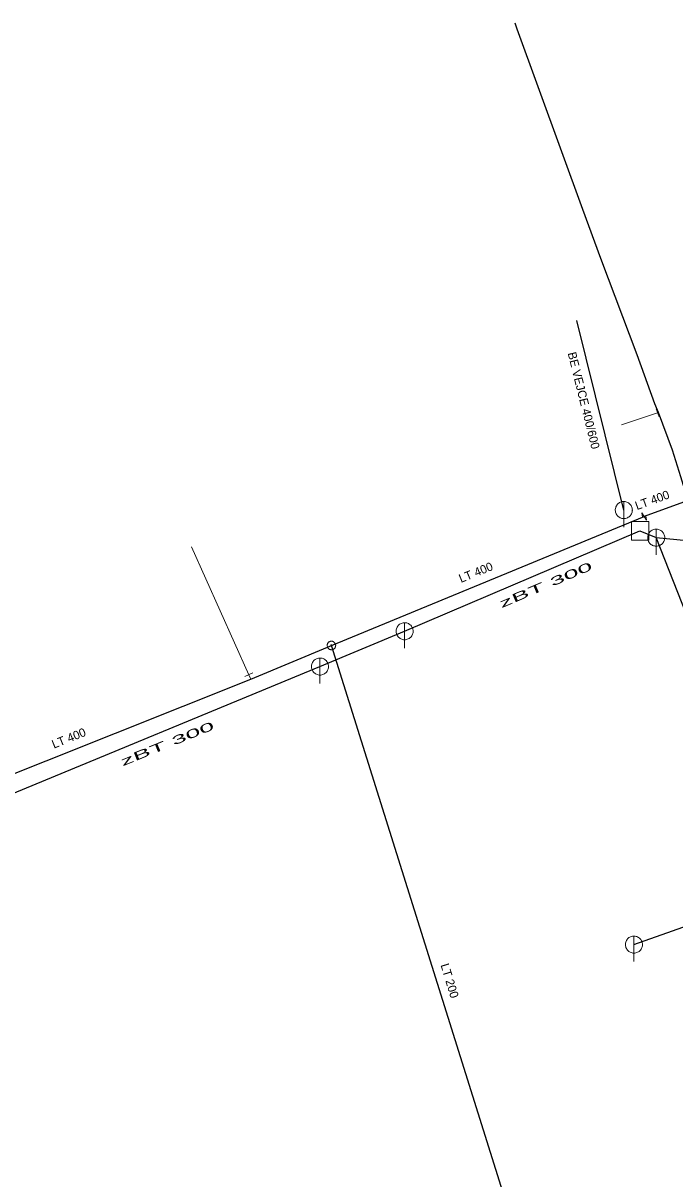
# Model space of a CAD drawing. Extents: x -690535 to -689974, y -975624 to -975325.
# Drawn here: x -690166.4 to -690089.9, y -975472.2 to -975336.7 of the extents above; entities that cross this region are included whole.
import ezdxf

# ---------------------------------------------------------------- set-up
doc = ezdxf.new("R2010")
doc.units = 0
doc.header["$LTSCALE"] = 0.4
for name, color, linetype, lineweight in [('1', 7, 'Continuous', 13), ('13', 7, 'Continuous', 13), ('14', 7, 'Continuous', 25), ('17', 7, 'Continuous', 25), ('22', 7, 'Continuous', 13), ('34', 7, 'Continuous', 13), ('47', 7, 'Continuous', 13)]:
    doc.layers.add(name, color=color, linetype=linetype, lineweight=lineweight)

msp = doc.modelspace()

# ---------------------------------------------------------------- linework, layer by layer
at = {"layer": '13'}
for p, q in [((-690091.956, -975382.406), (-690096.197, -975383.807)), ((-690139.915, -975413.104), (-690146.658, -975398.088))]:
    msp.add_line(p, q, dxfattribs=at)
at = {"layer": '14'}
for p, q in [((-690095.92, -975393.789), (-690101.415, -975371.588)), ((-690094.039, -975396.21), (-690092.12, -975397.03)), ((-690092.12, -975397.03), (-690082.941, -975397.9)), ((-690172.92, -975429.199), (-690131.567, -975412.142))]:
    msp.add_line(p, q, dxfattribs=at)
at = {"layer": '14', "lineweight": 13}
for p, q in [((-690091.866, -975382.373), (-690091.956, -975382.406)), ((-690139.673, -975413.635), (-690139.915, -975413.104))]:
    msp.add_line(p, q, dxfattribs=at)
at = {"layer": '14'}
for points in [[(-690131.567, -975412.142), (-690121.64, -975408), (-690094.039, -975396.21)], [(-690094.732, -975444.739), (-690075.94, -975438.079), (-690092.12, -975397.03)]]:
    msp.add_lwpolyline(points, dxfattribs=at)
at = {"layer": '17'}
for p in [(-690088.912, -975392.874), (-690130.226, -975409.671)]:
    msp.add_line(p, (-690093.531, -975394.548), dxfattribs=at)
for points in [[(-690088.634, -975391.824), (-690089.23, -975389.914), (-690090.217, -975386.78), (-690091.866, -975382.373), (-690092.267, -975381.329), (-690094.342, -975375.603), (-690098.616, -975364.307), (-690100.726, -975358.546), (-690108.436, -975337.406), (-690108.682, -975336.702)], [(-690179.591, -975429.529), (-690139.673, -975413.635), (-690130.226, -975409.671)], [(-690099.953, -975513.738), (-690104.725, -975490.907), (-690130.226, -975409.671)]]:
    msp.add_lwpolyline(points, dxfattribs=at)
at = {"layer": '22'}
for p, q in [((-690095.92, -975395.789), (-690095.919, -975392.789)), ((-690092.12, -975399.03), (-690092.119, -975396.03)), ((-690121.64, -975410), (-690121.639, -975407)), ((-690131.567, -975414.142), (-690131.566, -975411.142)), ((-690094.733, -975446.74), (-690094.732, -975443.74))]:
    msp.add_line(p, q, dxfattribs=at)
for points in [[(-690094.92, -975393.789), (-690094.925, -975393.68), (-690094.943, -975393.572), (-690094.973, -975393.466), (-690095.013, -975393.365), (-690095.065, -975393.268), (-690095.127, -975393.178), (-690095.199, -975393.095), (-690095.279, -975393.021), (-690095.367, -975392.955), (-690095.461, -975392.9), (-690095.561, -975392.855), (-690095.666, -975392.822), (-690095.773, -975392.8), (-690095.882, -975392.79), (-690095.992, -975392.792), (-690096.1, -975392.806), (-690096.207, -975392.831), (-690096.31, -975392.868), (-690096.408, -975392.917), (-690096.5, -975392.975), (-690096.586, -975393.044), (-690096.663, -975393.121), (-690096.732, -975393.207), (-690096.791, -975393.299), (-690096.839, -975393.397), (-690096.876, -975393.5), (-690096.902, -975393.607), (-690096.916, -975393.715), (-690096.919, -975393.825), (-690096.909, -975393.934), (-690096.888, -975394.041), (-690096.854, -975394.145), (-690096.81, -975394.245), (-690096.755, -975394.34), (-690096.689, -975394.428), (-690096.615, -975394.508), (-690096.532, -975394.58), (-690096.442, -975394.642), (-690096.346, -975394.694), (-690096.244, -975394.735), (-690096.139, -975394.765), (-690096.031, -975394.783), (-690095.921, -975394.789), (-690095.812, -975394.783), (-690095.704, -975394.765), (-690095.599, -975394.736), (-690095.497, -975394.695), (-690095.4, -975394.643), (-690095.31, -975394.581), (-690095.227, -975394.51), (-690095.152, -975394.43), (-690095.087, -975394.342), (-690095.031, -975394.248), (-690094.987, -975394.148), (-690094.953, -975394.044), (-690094.931, -975393.936), (-690094.921, -975393.827)], [(-690095.02, -975395.12), (-690092.987, -975395.12), (-690092.987, -975397.313), (-690095.02, -975397.313)], [(-690091.12, -975397.03), (-690091.125, -975396.921), (-690091.143, -975396.813), (-690091.173, -975396.707), (-690091.213, -975396.606), (-690091.265, -975396.509), (-690091.327, -975396.419), (-690091.399, -975396.336), (-690091.479, -975396.262), (-690091.567, -975396.196), (-690091.661, -975396.141), (-690091.761, -975396.096), (-690091.866, -975396.063), (-690091.973, -975396.041), (-690092.082, -975396.031), (-690092.192, -975396.033), (-690092.3, -975396.047), (-690092.407, -975396.072), (-690092.51, -975396.109), (-690092.608, -975396.158), (-690092.7, -975396.216), (-690092.786, -975396.285), (-690092.863, -975396.362), (-690092.932, -975396.448), (-690092.991, -975396.54), (-690093.039, -975396.638), (-690093.076, -975396.741), (-690093.102, -975396.848), (-690093.116, -975396.956), (-690093.119, -975397.066), (-690093.109, -975397.175), (-690093.088, -975397.282), (-690093.054, -975397.386), (-690093.01, -975397.486), (-690092.955, -975397.581), (-690092.889, -975397.669), (-690092.815, -975397.749), (-690092.732, -975397.821), (-690092.642, -975397.883), (-690092.546, -975397.935), (-690092.444, -975397.976), (-690092.339, -975398.006), (-690092.231, -975398.024), (-690092.121, -975398.03), (-690092.012, -975398.024), (-690091.904, -975398.006), (-690091.799, -975397.977), (-690091.697, -975397.936), (-690091.6, -975397.884), (-690091.51, -975397.822), (-690091.427, -975397.751), (-690091.352, -975397.671), (-690091.287, -975397.583), (-690091.231, -975397.489), (-690091.187, -975397.389), (-690091.153, -975397.285), (-690091.131, -975397.177), (-690091.121, -975397.068)], [(-690120.64, -975408), (-690120.645, -975407.891), (-690120.663, -975407.783), (-690120.693, -975407.677), (-690120.733, -975407.576), (-690120.785, -975407.479), (-690120.847, -975407.389), (-690120.919, -975407.306), (-690120.999, -975407.232), (-690121.087, -975407.166), (-690121.181, -975407.111), (-690121.281, -975407.066), (-690121.386, -975407.033), (-690121.493, -975407.011), (-690121.602, -975407.001), (-690121.712, -975407.003), (-690121.82, -975407.017), (-690121.927, -975407.042), (-690122.03, -975407.079), (-690122.128, -975407.128), (-690122.22, -975407.186), (-690122.306, -975407.255), (-690122.383, -975407.332), (-690122.452, -975407.418), (-690122.511, -975407.51), (-690122.559, -975407.608), (-690122.596, -975407.711), (-690122.622, -975407.818), (-690122.636, -975407.926), (-690122.639, -975408.036), (-690122.629, -975408.145), (-690122.608, -975408.252), (-690122.574, -975408.356), (-690122.53, -975408.456), (-690122.475, -975408.551), (-690122.409, -975408.639), (-690122.335, -975408.719), (-690122.252, -975408.791), (-690122.162, -975408.853), (-690122.066, -975408.905), (-690121.964, -975408.946), (-690121.859, -975408.976), (-690121.751, -975408.994), (-690121.641, -975409), (-690121.532, -975408.994), (-690121.424, -975408.976), (-690121.319, -975408.947), (-690121.217, -975408.906), (-690121.12, -975408.854), (-690121.03, -975408.792), (-690120.947, -975408.721), (-690120.872, -975408.641), (-690120.807, -975408.553), (-690120.751, -975408.459), (-690120.707, -975408.359), (-690120.673, -975408.255), (-690120.651, -975408.147), (-690120.641, -975408.038)], [(-690130.567, -975412.142), (-690130.572, -975412.033), (-690130.59, -975411.925), (-690130.62, -975411.819), (-690130.66, -975411.718), (-690130.712, -975411.621), (-690130.774, -975411.531), (-690130.846, -975411.448), (-690130.926, -975411.374), (-690131.014, -975411.308), (-690131.108, -975411.253), (-690131.208, -975411.208), (-690131.313, -975411.175), (-690131.42, -975411.153), (-690131.529, -975411.143), (-690131.639, -975411.145), (-690131.747, -975411.159), (-690131.854, -975411.184), (-690131.957, -975411.221), (-690132.055, -975411.27), (-690132.147, -975411.328), (-690132.233, -975411.397), (-690132.31, -975411.474), (-690132.379, -975411.56), (-690132.438, -975411.652), (-690132.486, -975411.75), (-690132.523, -975411.853), (-690132.549, -975411.96), (-690132.563, -975412.068), (-690132.566, -975412.178), (-690132.556, -975412.287), (-690132.535, -975412.394), (-690132.501, -975412.498), (-690132.457, -975412.598), (-690132.402, -975412.693), (-690132.336, -975412.781), (-690132.262, -975412.861), (-690132.179, -975412.933), (-690132.089, -975412.995), (-690131.993, -975413.047), (-690131.891, -975413.088), (-690131.786, -975413.118), (-690131.678, -975413.136), (-690131.568, -975413.142), (-690131.459, -975413.136), (-690131.351, -975413.118), (-690131.246, -975413.089), (-690131.144, -975413.048), (-690131.047, -975412.996), (-690130.957, -975412.934), (-690130.874, -975412.863), (-690130.799, -975412.783), (-690130.734, -975412.695), (-690130.678, -975412.601), (-690130.634, -975412.501), (-690130.6, -975412.397), (-690130.578, -975412.289), (-690130.568, -975412.18)], [(-690093.733, -975444.74), (-690093.738, -975444.631), (-690093.756, -975444.523), (-690093.786, -975444.417), (-690093.826, -975444.316), (-690093.878, -975444.219), (-690093.94, -975444.129), (-690094.012, -975444.046), (-690094.092, -975443.972), (-690094.18, -975443.906), (-690094.274, -975443.851), (-690094.374, -975443.806), (-690094.479, -975443.773), (-690094.586, -975443.751), (-690094.695, -975443.741), (-690094.805, -975443.743), (-690094.913, -975443.757), (-690095.02, -975443.782), (-690095.123, -975443.819), (-690095.221, -975443.868), (-690095.313, -975443.926), (-690095.399, -975443.995), (-690095.476, -975444.072), (-690095.545, -975444.158), (-690095.604, -975444.25), (-690095.652, -975444.348), (-690095.689, -975444.451), (-690095.715, -975444.558), (-690095.729, -975444.666), (-690095.732, -975444.776), (-690095.722, -975444.885), (-690095.701, -975444.992), (-690095.667, -975445.096), (-690095.623, -975445.196), (-690095.568, -975445.291), (-690095.502, -975445.379), (-690095.428, -975445.459), (-690095.345, -975445.531), (-690095.255, -975445.593), (-690095.159, -975445.645), (-690095.057, -975445.686), (-690094.952, -975445.716), (-690094.844, -975445.734), (-690094.734, -975445.74), (-690094.625, -975445.734), (-690094.517, -975445.716), (-690094.412, -975445.687), (-690094.31, -975445.646), (-690094.213, -975445.594), (-690094.123, -975445.532), (-690094.04, -975445.461), (-690093.965, -975445.381), (-690093.9, -975445.293), (-690093.844, -975445.199), (-690093.8, -975445.099), (-690093.766, -975444.995), (-690093.744, -975444.887), (-690093.734, -975444.778)]]:
    msp.add_lwpolyline(points, close=True, dxfattribs=at)
at = {"layer": '34'}
for p, q in [((-690091.779, -975382.873), (-690092.132, -975381.938)), ((-690140.365, -975413.32), (-690139.464, -975412.887))]:
    msp.add_line(p, q, dxfattribs=at)
at = {"layer": '47'}
msp.add_line((-690093.268, -975394.984), (-690093.342, -975394.479), dxfattribs=at)
msp.add_lwpolyline([(-690093.268, -975394.984), (-690093.793, -975394.111), (-690093.719, -975394.616)], dxfattribs=at)
for points in [[(-690129.764, -975409.477), (-690129.787, -975409.43), (-690129.815, -975409.385), (-690129.847, -975409.345), (-690129.883, -975409.306), (-690129.923, -975409.272), (-690129.967, -975409.243), (-690130.013, -975409.219), (-690130.061, -975409.199), (-690130.111, -975409.184), (-690130.163, -975409.174), (-690130.215, -975409.171), (-690130.267, -975409.173), (-690130.319, -975409.179), (-690130.37, -975409.192), (-690130.419, -975409.209), (-690130.466, -975409.232), (-690130.511, -975409.26), (-690130.552, -975409.292), (-690130.59, -975409.328), (-690130.624, -975409.368), (-690130.653, -975409.412), (-690130.678, -975409.458), (-690130.698, -975409.506), (-690130.713, -975409.556), (-690130.722, -975409.608), (-690130.725, -975409.66), (-690130.724, -975409.713), (-690130.717, -975409.764), (-690130.704, -975409.815), (-690130.687, -975409.864), (-690130.664, -975409.911), (-690130.636, -975409.956), (-690130.604, -975409.998), (-690130.568, -975410.035), (-690130.528, -975410.069), (-690130.485, -975410.098), (-690130.439, -975410.123), (-690130.39, -975410.143), (-690130.34, -975410.158), (-690130.288, -975410.167), (-690130.236, -975410.17), (-690130.184, -975410.169), (-690130.132, -975410.162), (-690130.081, -975410.149), (-690130.032, -975410.132), (-690129.985, -975410.109), (-690129.94, -975410.081), (-690129.899, -975410.05), (-690129.861, -975410.013), (-690129.827, -975409.973), (-690129.798, -975409.93), (-690129.774, -975409.884), (-690129.754, -975409.836), (-690129.739, -975409.785), (-690129.729, -975409.733), (-690129.726, -975409.681), (-690129.728, -975409.63), (-690129.734, -975409.577), (-690129.747, -975409.526)], [(-690130.15, -975409.639), (-690130.153, -975409.63), (-690130.158, -975409.624), (-690130.163, -975409.617), (-690130.169, -975409.611), (-690130.176, -975409.605), (-690130.183, -975409.601), (-690130.191, -975409.596), (-690130.198, -975409.593), (-690130.207, -975409.591), (-690130.215, -975409.589), (-690130.224, -975409.589), (-690130.233, -975409.589), (-690130.241, -975409.59), (-690130.249, -975409.591), (-690130.257, -975409.595), (-690130.266, -975409.598), (-690130.272, -975409.603), (-690130.279, -975409.608), (-690130.285, -975409.614), (-690130.291, -975409.621), (-690130.295, -975409.628), (-690130.3, -975409.636), (-690130.303, -975409.643), (-690130.306, -975409.652), (-690130.307, -975409.66), (-690130.307, -975409.669), (-690130.307, -975409.678), (-690130.306, -975409.686), (-690130.305, -975409.694), (-690130.301, -975409.702), (-690130.298, -975409.711), (-690130.293, -975409.717), (-690130.288, -975409.724), (-690130.282, -975409.73), (-690130.275, -975409.736), (-690130.269, -975409.741), (-690130.26, -975409.745), (-690130.253, -975409.748), (-690130.244, -975409.751), (-690130.236, -975409.752), (-690130.227, -975409.752), (-690130.218, -975409.752), (-690130.21, -975409.751), (-690130.202, -975409.75), (-690130.194, -975409.746), (-690130.185, -975409.743), (-690130.179, -975409.738), (-690130.172, -975409.733), (-690130.166, -975409.727), (-690130.16, -975409.72), (-690130.155, -975409.714), (-690130.151, -975409.705), (-690130.148, -975409.698), (-690130.146, -975409.689), (-690130.144, -975409.681), (-690130.144, -975409.672), (-690130.144, -975409.663), (-690130.145, -975409.655), (-690130.146, -975409.647)]]:
    msp.add_lwpolyline(points, close=True, dxfattribs=at)

# ---------------------------------------------------------------- texts
at = {"layer": '1'}
for s, rotation, p in [('BE VEJCE 400/600', 284, (-690102.516, -975375.4)), ('LT 400', 20, (-690094.378, -975393.806)), ('LT 400', 22, (-690115.027, -975402.341)), ('LT 400', 22, (-690162.783, -975421.776)), ('LT 200', 287, (-690117.433, -975447.131))]:
    msp.add_text(s, height=1, rotation=rotation, dxfattribs=at).set_placement(p)
at = {"layer": '1', "width": 2.35}
for rotation, p in [(23, (-690110.278, -975405.304)), (22, (-690154.721, -975423.84))]:
    msp.add_text('zBT 300 ', height=1, rotation=rotation, dxfattribs=at).set_placement(p)

doc.saveas('drawing.dxf')
